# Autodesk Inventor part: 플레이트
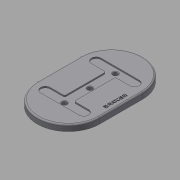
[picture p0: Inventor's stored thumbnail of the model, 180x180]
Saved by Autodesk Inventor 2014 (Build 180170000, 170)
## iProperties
Created: 2016-08
Part Number: 플레이트
Material: Aluminum 6061
Document SubType Name: Modeling
Designer: mduedu
Density: 1 g/cm^3
Appearance: Default
Mass: 304.486 g
Surface Area: 591.117 cm^2
Volume: 304.486 cm^3
Author: mduedu
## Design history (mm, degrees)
sketch "스케치1" dims "d0" = 220, "d2" = 130
  geometry: L1 (45, 65)-(-45, 65); L2 (-45, 65)-(-45, -65); L3 (-45, -65)-(45, -65); L4 (45, -65)-(45, 65); L5 (45, 65)-(-45, -65); L6 (-45, 65)-(45, -65); 5 further points
  constraints: 12 end point, 5 midpoint, 2 parallel, 2 vertical alignment, 1 coincident, 1 horizontal, 1 perpendicular, 4 other
extrude "돌출1" new body sketch "스케치1" distance "d3" = 13; taper "d4" = 0 deg
sketch "스케치2"
  geometry: L1 (-63, -50)-(63, -50); L2 (63, -50)-(63, 50); L3 (63, 50)-(-63, 50); L4 (-63, 50)-(-63, -50); L5 (-63, -50)-(63, 50); L6 (63, -50)-(-63, 50); L7 (-63, 50)-(-43, 50); L8 (-43, 50)-(-43, -50); L9 (-43, -50)-(-63, -50); L10 (-63, -50)-(-63, 50); L11 (63, 50)-(43, 50); L12 (43, 50)-(43, -50); L13 (43, -50)-(63, -50); L14 (63, -50)-(63, 50); L15 (-43, -10)-(43, -10); L16 (43, -10)-(43, 10); L17 (43, 10)-(-43, 10); L18 (-43, 10)-(-43, -10); L19 (-43, -10)-(43, 10); L20 (43, -10)-(-43, 10); 1 further point
  constraints: 40 end point, 8 parallel, 4 horizontal, 4 midpoint, 4 perpendicular, 3 point on line
  dimensions: "d18" = 126 distance of L3.end L2.end; "d19" = 100 distance of L2.end L1.end; "d20" = 20 distance of L8.end L9.end; "d21" = 20 distance of L12.end L13.end (= d20); "d22" = 20 distance of L15.end L16.end
extrude "돌출3" cut sketch "스케치2" distance "d23" = 3; taper "d24" = 0 deg
fillet "모깎기2"
fillet "모깎기3"
fillet "모깎기4"
fillet "모깎기5"
fillet "모깎기6" dims "d25" = 3
sketch "스케치4"
  geometry: L1 (-43, -40)-(-43, -13) reference; L2 (-40, -10)-(40, -10) reference; L3 (43, -13)-(43, -40) reference; L4 (63, -40)-(63, 40) reference; L5 (43, 40)-(43, 13) reference; L6 (40, 10)-(-40, 10) reference; L7 (-43, 13)-(-43, 40) reference; L8 (-63, 40)-(-63, -40) reference; L9 (45, -65)-(-45, -65) reference; L10 (-45, 65)-(45, 65) reference; L11 (-53, 40)-(-53, -40); L12 (53, 40)-(53, -40); L13 (-53, 0)-(53, 0); C1 r 5 at (-53, 0); C2 r 5 at (0, 0); C3 r 5 at (53, 0); A1 r 10 centre (-53, -40) between (-63, -40) and (-43, -40) reference; A2 r 3 centre (-40, -13) between (-40, -10) and (-43, -13) reference; A3 r 3 centre (40, -13) between (43, -13) and (40, -10) reference; A4 r 10 centre (53, -40) between (43, -40) and (63, -40) reference; A5 r 10 centre (53, 40) between (63, 40) and (43, 40) reference; A6 r 3 centre (40, 13) between (40, 10) and (43, 13) reference; A7 r 3 centre (-40, 13) between (-43, 13) and (-40, 10) reference; A8 r 10 centre (-53, 40) between (-43, 40) and (-63, 40) reference; A9 r 65 centre (45, 0) between (45, -65) and (45, 65) reference; A10 r 65 centre (-45, 0) between (-45, 65) and (-45, -65) reference; 1 further point
  constraints: 6 end point, 3 centre point, 3 coincident, 2 midpoint, 1 parallel, 1 perpendicular
  dimensions: "d26" = 10 diameter of C1; "d27" = 10 diameter of C2; "d28" = 10 diameter of C3
extrude "돌출4" cut sketch "스케치4" stored distance "d29" = 3; taper "d30" = 0 deg
chamfer "모따기2" distance "d31" = 1; stored, may be unused: second distance "d32" = 2, angle "d33" = 45 deg
fillet "모깎기1" dims "d14" = 3
sketch "스케치3"
  geometry: L1 (-45, -65)-(45, -65) reference; 2 further points
  constraints: 1 vertical alignment, 1 other
  dimensions: "d15" = 12 distance from line of point (0, -53) L1
feature "엠보싱1" sketch "스케치3" dims "d0" = 220, "d2" = 130, "d16" = 0.5, "d17" = 0
node "솔리드1"
node "절단 모서리 투영1"
